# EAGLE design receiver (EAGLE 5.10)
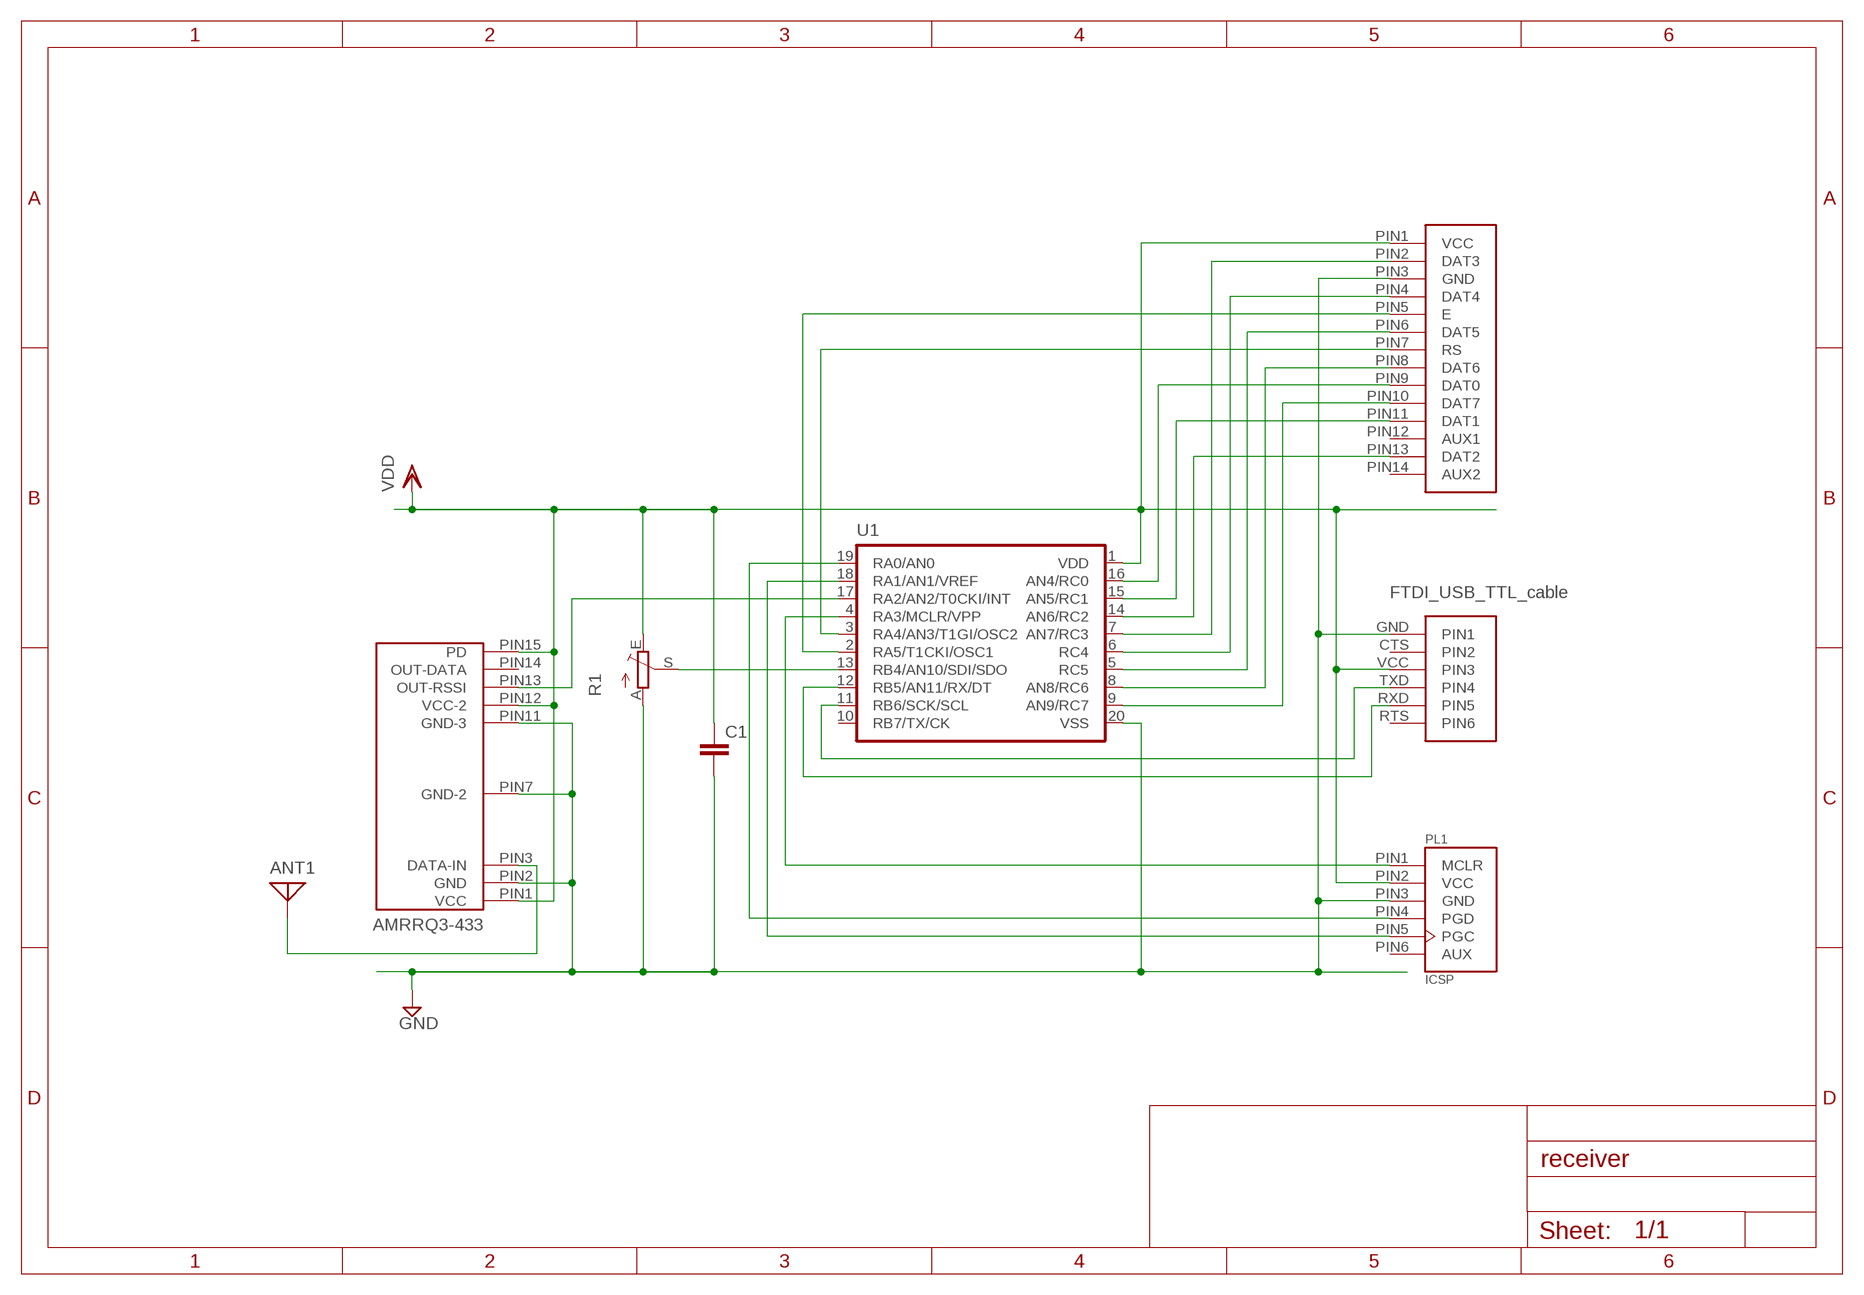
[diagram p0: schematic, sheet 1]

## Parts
ANT1  ANTENNA  [PAD-01]
C1  C2.5/2  [C2.5-2]
PL1  ICSP  [6X1-ICSP]
R1  TRIM_EU-LI10  [LI10]
U1  PIC16F6XX  [DIL20]
U$1  AMRRQ3-433  [AMRRQ3-433]
U$2  FTDI_USB_TTL_CABLE  [FTDI_USB_TTL_CABLE]
U$3  7X2DISPLAY  [7X2DISPLAY]

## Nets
GND: C1.2 PL1.PIN3(GND) R1.A U1.20(VSS) U$1.PIN2(GND) U$1.PIN7(GND-2) U$1.PIN11(GND-3) U$2.GND(PIN1) U$3.PIN3(GND)
N$1: U1.12(RB5/AN11/RX/DT) U$2.RXD(PIN5)
N$3: U1.17(RA2/AN2/T0CKI/INT) U$1.PIN13(OUT-RSSI)
N$4: U1.2(RA5/T1CKI/OSC1) U$3.PIN5(E)
N$7: ANT1.1 U$1.PIN3(DATA-IN)
N$8: U1.11(RB6/SCK/SCL) U$2.TXD(PIN4)
N$9: PL1.PIN5(PGC) U1.18(RA1/AN1/VREF)
N$10: U1.3(RA4/AN3/T1GI/OSC2) U$3.PIN7(RS)
N$11: PL1.PIN4(PGD) U1.19(RA0/AN0)
N$12: PL1.PIN1(MCLR) U1.4(RA3/MCLR/VPP)
N$14: R1.S U1.13(RB4/AN10/SDI/SDO)
N$16: U1.16(AN4/RC0) U$3.PIN9(DAT0)
N$17: U1.15(AN5/RC1) U$3.PIN11(DAT1)
N$18: U1.14(AN6/RC2) U$3.PIN13(DAT2)
N$19: U1.7(AN7/RC3) U$3.PIN2(DAT3)
N$20: U1.6(RC4) U$3.PIN4(DAT4)
N$21: U1.5(RC5) U$3.PIN6(DAT5)
N$22: U1.8(AN8/RC6) U$3.PIN8(DAT6)
N$23: U1.9(AN9/RC7) U$3.PIN10(DAT7)
VDD: C1.1 PL1.PIN2(VCC) R1.E U1.1(VDD) U$1.PIN1(VCC) U$1.PIN12(VCC-2) U$1.PIN15(PD) U$2.VCC(PIN3) U$3.PIN1(VCC)
Unconnected: PL1.PIN6(AUX) U1.10(RB7/TX/CK) U$1.PIN14(OUT-DATA) U$2.CTS(PIN2) U$2.RTS(PIN6) U$3.PIN12(AUX1) U$3.PIN14(AUX2)

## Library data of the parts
ANT1 = discrete:ANTENNA: Antenna
C1 = capacitor-wima:C: CAPACITOR
PL1 = jason-test:ICSP: Microchip ICSP header
R1 = pot:TRIM_EU-: POTENTIOMETER
U1 = pic16f690:PIC16F6XX
U$1 = AMRRQ3-433:AMRRQ3-433
U$2 = USBTTL_cable:FTDI_USB_TTL_CABLE
U$3 = display_connector:7X2DISPLAY

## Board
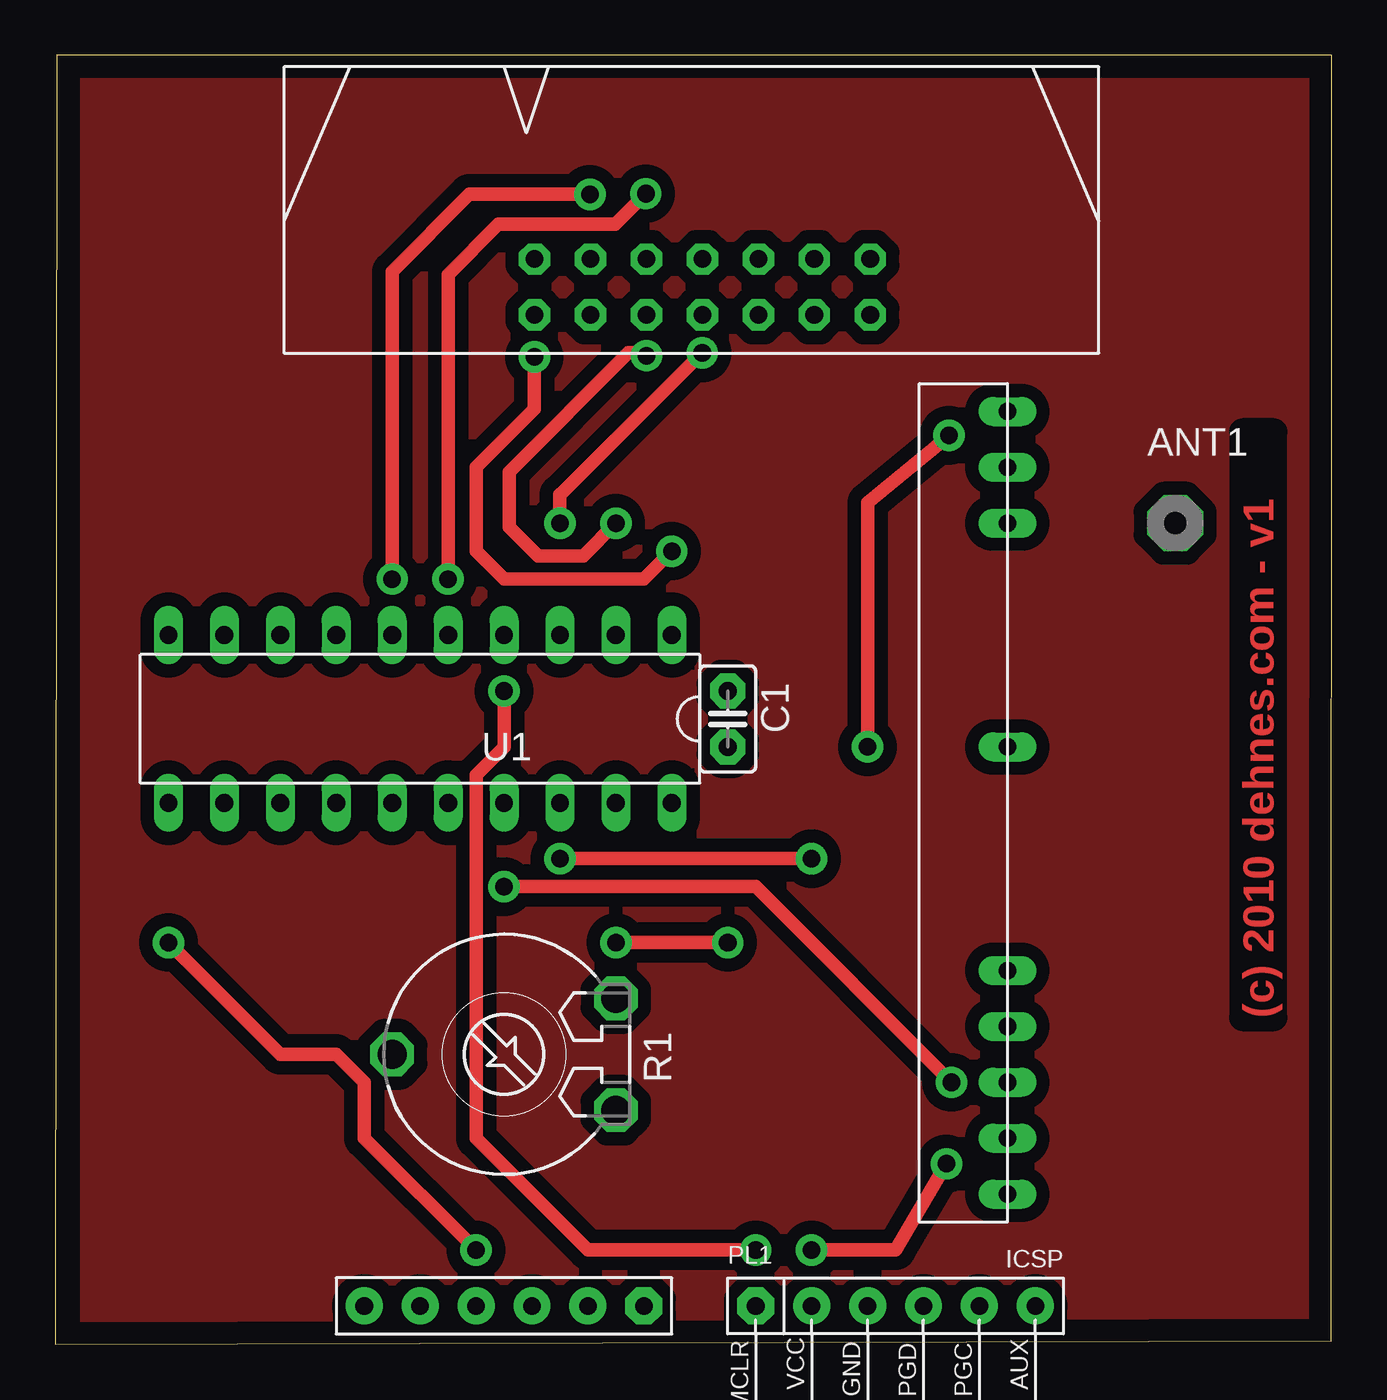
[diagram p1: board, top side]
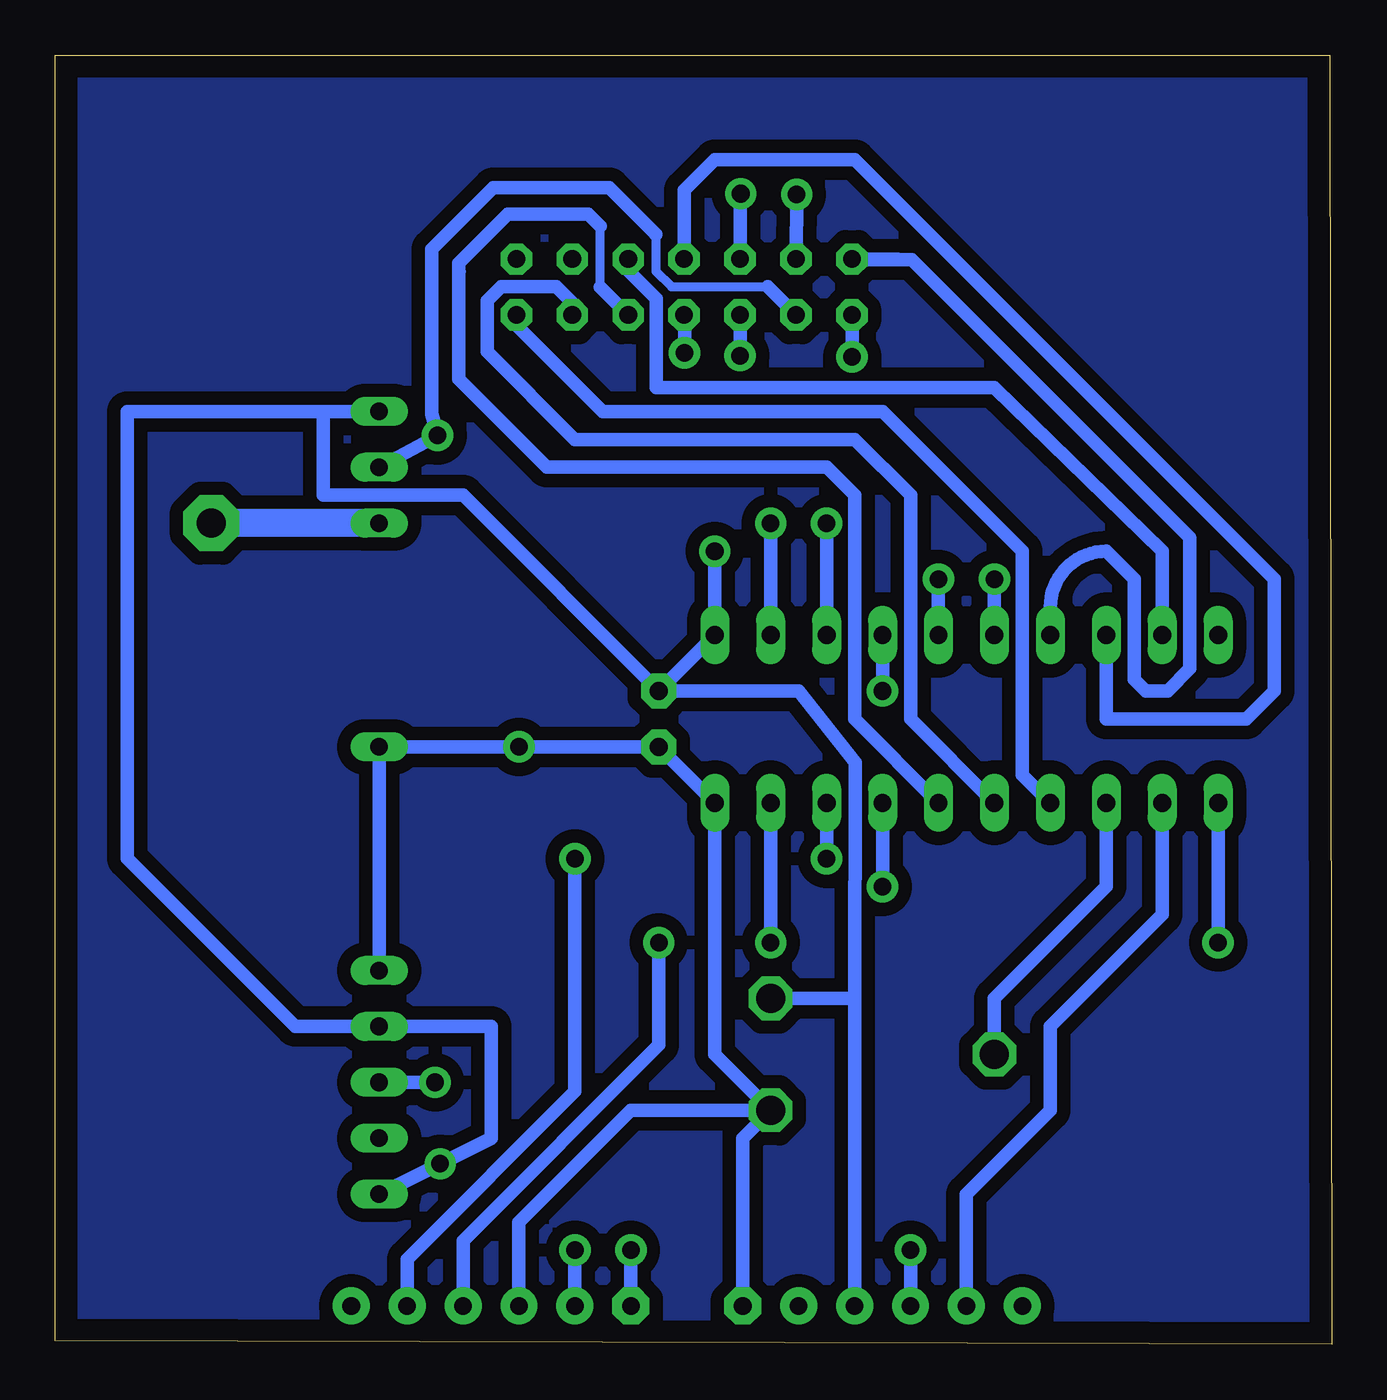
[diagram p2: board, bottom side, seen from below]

Size 57.97 x 58.58 mm. Coordinates in mm from the lower left corner, seen from the top.
Outline: 0,0 57.96,0.17 57.97,58.58 0.07,58.58 0,0
Copper layers (1*16): Top 0.035mm / dielectric 1.5mm / Bottom 0.035mm
Design rules "default": minimum track width 10mil, minimum drill 24mil, track to track 8mil, track to pad 8mil, pad to pad 8mil, via to via 8mil, smd to smd 8mil, copper to edge 40mil, drill to drill 8mil, minimum pad ring 10mil, minimum via ring 8mil, stop-mask expansion 4mil, vias tented up to drill 0mil, thermal gap 10mil

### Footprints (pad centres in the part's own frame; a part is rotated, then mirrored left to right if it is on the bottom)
PAD-01 = drill 1.321 pad 2.54 octagon: 1 0,0
C2.5-2 = drill 0.813 pad 1.6 octagon: 1 -1.27,0; 2 1.27,0
6X1-ICSP = drill 0.8 pad 1.676 octagon: PIN1 -6.35,0 | drill 0.8 pad 1.676 round: PIN2 -3.81,0; PIN3 -1.27,0; PIN4 1.27,0; PIN5 3.81,0; PIN6 6.35,0
LI10 = drill 1.321 octagon: A -2.54,-5.08; E 2.54,-5.08; S 0,5.08
DIL20 = drill 0.813 long: 1 -11.43,-3.81; 2 -8.89,-3.81; 3 -6.35,-3.81; 4 -3.81,-3.81; 5 -1.27,-3.81; 6 1.27,-3.81; 7 3.81,-3.81; 8 6.35,-3.81; 9 8.89,-3.81; 10 11.43,-3.81; 11 11.43,3.81; 12 8.89,3.81; 13 6.35,3.81; 14 3.81,3.81; 15 1.27,3.81; 16 -1.27,3.81; 17 -3.81,3.81; 18 -6.35,3.81; 19 -8.89,3.81; 20 -11.43,3.81
AMRRQ3-433 = drill 0.8 long: PIN1 0,17.78; PIN2 0,15.24; PIN3 0,12.7; PIN7 0,2.54; PIN11 0,-7.62; PIN12 0,-10.16; PIN13 0,-12.7; PIN14 0,-15.24; PIN15 0,-17.78
FTDI_USB_TTL_CABLE = drill 0.8 pad 1.676 round: CTS 0,1.27; RTS 0,-8.89; RXD 0,-6.35; TXD 0,-3.81; VCC 0,-1.27 | drill 0.8 pad 1.676 octagon: GND 0,3.81
7X2DISPLAY = drill 0.8 pad 1.422 octagon: PIN1 -1.27,7.62; PIN2 1.27,7.62; PIN3 -1.27,5.08; PIN4 1.27,5.08; PIN5 -1.27,2.54; PIN6 1.27,2.54; PIN7 -1.27,0; PIN8 1.27,0; PIN9 -1.27,-2.54; PIN10 1.27,-2.54; PIN11 -1.27,-5.08; PIN12 1.27,-5.08; PIN13 -1.27,-7.62; PIN14 1.27,-7.62

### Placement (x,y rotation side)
ANT1  50.87,37.31 0 top
C1  30.55,28.42 270 top
PL1  38.17,1.75 0 top
R1  20.39,13.18 90 top
U1  16.58,28.42 180 top
U$1  43.25,24.61 0 top
U$2  22.93,1.75 270 top
U$3  29.4,48.04 90 top

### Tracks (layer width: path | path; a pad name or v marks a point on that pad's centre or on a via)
GND  (via drill 0.8 pad 1.42)
  Top 0.61: v40.6,41.3 36.9,38.24 v36.9,27.15
  Bottom 0.406: 30.68,50.44 30.68,48.76 29.97,48.05 25.6,48.05
  Bottom 0.61: R1.A 28.01,13.18 U1.20 C1.2 v36.9,27.15 U$1.PIN7 U$1.PIN11 | R1.A 26.74,9.37 U$2.GND | PL1.PIN3 36.9,5.56 31.82,10.64 R1.A | 25.6,48.05 U$3.PIN3 | 30.7,50.42 30.68,50.44 32.79,52.55 38.07,52.55 40.86,49.76 40.86,42.26 v40.6,41.3 43.25,39.87 U$1.PIN2
N$1
  Bottom 0.61: U$2.RXD 16.58,6.83 12.77,10.64 12.77,14.45 7.69,19.53 U1.12
N$2
  pour Bottom (isolate 0.61): 0.07,58.57 57.94,58.57 57.94,0.19 0.07,0.19
N$3  (via drill 0.8 pad 1.42)
  Top 0.61: v20.39,20.8 31.82,20.8 v40.71,11.91
  Bottom 0.61: v20.39,20.8 U1.17 | v40.71,11.91 U$1.PIN13
N$4  (via drill 0.8 pad 1.42)
  Top 0.61: v26.86,44.92 26.85,45.05 26.03,45.05 20.62,39.64 20.62,37.14 21.94,35.82 23.98,35.82 v25.47,37.31
  Bottom 0.61: U$3.PIN5 v26.86,44.92 26.85,45.05 | v25.47,37.31 U1.2
N$7
  Bottom 1.27: U$1.PIN3 ANT1.1
N$8  (via drill 0.8 pad 1.42)
  Top 0.61: v5.15,18.26 10.23,13.18 12.77,13.18 14.04,11.91 14.04,9.37 v19.12,4.29
  Bottom 0.61: v5.15,18.26 U1.11 | U$2.TXD v19.12,4.29
N$9  (via drill 0.8 pad 1.42)
  Top 0.61: v34.36,22.07 v22.93,22.07
  Bottom 0.61: PL1.PIN5 41.98,3.87 34.36,11.49 v34.36,22.07 | v22.93,22.07 U1.18
N$10  (via drill 0.8 pad 1.42)
  Top 0.61: v22.93,37.31 22.93,38.6 22.94,38.6 v29.39,45.05
  Bottom 0.254: v29.38,45.04 29.28,44.93 v29.39,45.05
  Bottom 0.61: U1.3 v22.93,37.31 | U$3.PIN7 29.38,46.75 v29.38,45.04
N$11  (via drill 0.8 pad 1.42)
  Top 0.61: v30.55,18.26 v25.47,18.26
  Bottom 0.61: PL1.PIN4 39.44,4.71 30.55,13.6 v30.55,18.26 | v25.47,18.26 U1.19
N$12  (via drill 0.8 pad 1.42)
  Top 0.61: v20.39,29.69 20.39,27.15 19.12,25.88 19.12,9.37 24.2,4.29 v31.82,4.29
  Bottom 0.61: v20.39,29.69 U1.4 | v31.82,4.29 PL1.PIN1
N$14
  Bottom 0.61: R1.S 15.31,15.72 10.23,20.8 U1.13
N$16
  Bottom 0.254: 39.64,48.74 39.44,48.74
  Bottom 0.406: 33.2,48.03 33.2,50.8
  Bottom 0.61: U1.16 21.66,28.42 21.66,38.58 22.93,39.85 35.63,39.85 39.64,43.86 39.64,48.74 39.64,49.13 37.42,51.35 33.75,51.35 33.2,50.8 | U$3.PIN9 33.2,48.03
N$17
  Bottom 0.61: U1.15 19.12,28.42 19.12,38.58 21.66,41.12 34.36,41.12 38.35,45.11 38.35,47.42 37.71,48.06 35.21,48.06 34.48,47.33 U$3.PIN11
N$18
  Bottom 0.61: U1.14 14.04,25.88 14.04,36.04 20.39,42.39 33.09,42.39 37.02,46.32 U$3.PIN13
N$19
  Bottom 0.61: 19.69,49.31 U$3.PIN2 21.75,49.28 19.06,49.28 6.45,36.67 6.45,36.65 6.43,36.63 6.43,30.7 7.44,29.69 8.44,29.69 8.96,30.21 8.96,34.77 10.23,36.04 arc-90 12.77,33.5 U1.7
N$20  (via drill 0.8 pad 1.42)
  Top 0.61: v15.31,34.77 15.31,48.74 18.82,52.25 v24.29,52.25
  Bottom 0.61: U1.6 v15.31,34.77 | U$3.PIN4 24.3,49.33 v24.29,52.25
N$21  (via drill 0.8 pad 1.42)
  Top 0.61: v17.85,34.77 17.85,48.61 20.13,50.89 25.44,50.89 v26.83,52.28 26.85,52.3
  Bottom 0.61: U1.5 v17.85,34.77 | U$3.PIN6 26.86,52.25 v26.83,52.28
N$22
  Bottom 0.61: U$3.PIN8 29.4,52.43 28.01,53.82 21.66,53.82 2.61,34.77 2.61,29.69 3.88,28.42 10.23,28.42 U1.8
N$23
  Bottom 0.61: U1.9 7.69,36.04 15.31,43.46 30.67,43.46 30.67,47.52 31.94,48.79 U$3.PIN10
SOMENET2
  pour Top (isolate 0.61): 1.34,57.63 57.22,57.63 57.22,0.48 1.34,0.48
VDD  (via drill 0.8 pad 1.42)
  Top 0.61: v34.36,4.29 38.17,4.29 v40.48,8.21 | v21.77,44.86 21.76,42.49 19.12,39.85 19.12,36.04 20.39,34.77 26.74,34.77 v28.01,36.04
  Bottom 0.61: C1.1 U1.1 v28.01,36.04 | U$2.VCC 21.66,15.72 | 21.66,15.72 21.62,26.44 24.2,29.69 C1.1 | 21.66,15.72 R1.E | U$1.PIN15 v40.48,8.21 38.17,9.37 38.17,14.45 U$1.PIN12 47.06,14.45 54.68,22.07 54.68,42.39 U$1.PIN1 45.79,42.39 45.79,38.58 39.44,38.58 C1.1 | v34.36,4.29 PL1.PIN2 | U$3.PIN1 21.76,46.77 v21.77,44.86

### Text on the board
Top: (c) 2010 dehnes.com - v1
